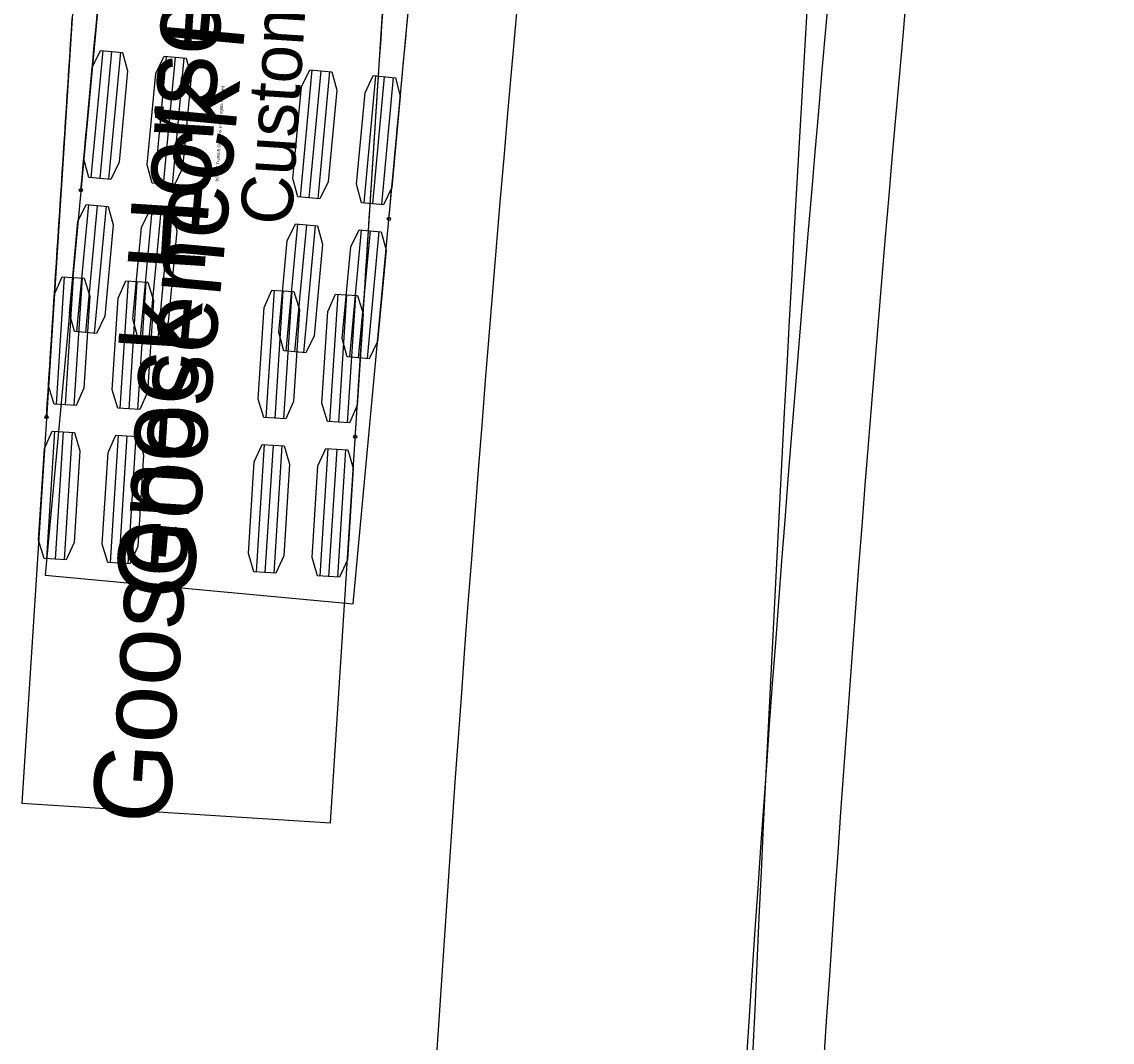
# Model space of a CAD drawing. Extents: x -14 to 1565148, y -25 to 642856.
# Drawn here: x 1564790.38 to 1564818.58, y 636076.25 to 636102.63 of the extents above; entities that cross this region are included whole.
import ezdxf

# ---------------------------------------------------------------- set-up
doc = ezdxf.new("R2010")
doc.units = 0
for name, color, linetype in [('DR_P_Drainage_Area', 7, 'Continuous'), ('DR_P_Underdrain', 7, 'Continuous'), ('GE_P_Alignment', 7, 'Continuous'), ('MT_P_Cells', 7, 'Continuous'), ('PF_P_Grade_Line', 7, 'Continuous'), ('PV_X_EOP', 7, 'Continuous')]:
    doc.layers.add(name, color=color, linetype=linetype)

msp = doc.modelspace()

# ---------------------------------------------------------------- linework, layer by layer
at = {"layer": 'DR_P_Drainage_Area'}
msp.add_arc((1566787.273, 635986.808), 1980, 175.493678, 179.898828, dxfattribs=at)
at = {"layer": 'DR_P_Underdrain'}
msp.add_arc((1565898.839, 636005.315), 1090, 172.336069, 179.46316, dxfattribs=at)
at = {"layer": 'GE_P_Alignment'}
msp.add_arc((1565898.839, 636005.315), 1092, 172.336069, 179.46316, dxfattribs=at)
at = {"layer": 'MT_P_Cells'}
for p, q in [((1564792.682, 636118.358), (1564790.385, 636082.431)), ((1564798.368, 636081.921), (1564800.666, 636117.847)), ((1564791.484, 636096.039), (1564791.274, 636092.745)), ((1564791.713, 636096.024), (1564791.503, 636092.731)), ((1564791.942, 636096.009), (1564791.731, 636092.716)), ((1564793.131, 636095.933), (1564792.92, 636092.64)), ((1564793.36, 636095.919), (1564793.149, 636092.626)), ((1564793.588, 636095.904), (1564793.378, 636092.611)), ((1564796.907, 636095.692), (1564796.696, 636092.399)), ((1564797.135, 636095.677), (1564796.925, 636092.384)), ((1564797.364, 636095.663), (1564797.153, 636092.369)), ((1564798.553, 636095.587), (1564798.343, 636092.293)), ((1564798.782, 636095.572), (1564798.571, 636092.279)), ((1564799.011, 636095.557), (1564798.8, 636092.264)), ((1564791.229, 636092.047), (1564791.019, 636088.754)), ((1564791.458, 636092.032), (1564791.247, 636088.739)), ((1564791.687, 636092.018), (1564791.476, 636088.724)), ((1564792.876, 636091.942), (1564792.665, 636088.648)), ((1564793.104, 636091.927), (1564792.894, 636088.634)), ((1564793.333, 636091.912), (1564793.123, 636088.619)), ((1564796.651, 636091.7), (1564796.441, 636088.407)), ((1564796.88, 636091.685), (1564796.669, 636088.392)), ((1564797.109, 636091.671), (1564796.898, 636088.378)), ((1564798.298, 636091.595), (1564798.087, 636088.302)), ((1564798.527, 636091.58), (1564798.316, 636088.287)), ((1564798.755, 636091.566), (1564798.545, 636088.272)), ((1564790.385, 636082.431), (1564798.368, 636081.921))]:
    msp.add_line(p, q, dxfattribs=at)
for points in [[(1564799.006, 636091.9), (1564799.028, 636092.233), (1564799.049, 636092.566), (1564799.07, 636092.898), (1564799.092, 636093.23), (1564799.113, 636093.563), (1564799.134, 636093.895), (1564799.155, 636094.227), (1564799.177, 636094.559), (1564799.198, 636094.891), (1564799.219, 636095.223), (1564799.241, 636095.555), (1564799.262, 636095.887), (1564799.283, 636096.22), (1564799.305, 636096.552), (1564799.326, 636096.884), (1564799.347, 636097.216), (1564799.369, 636097.548), (1564799.39, 636097.88), (1564799.412, 636098.211), (1564799.433, 636098.543), (1564799.455, 636098.875), (1564799.476, 636099.207), (1564799.498, 636099.539), (1564799.519, 636099.871), (1564799.541, 636100.203), (1564799.563, 636100.535), (1564799.585, 636100.866), (1564799.606, 636101.198), (1564799.628, 636101.53), (1564799.65, 636101.862), (1564799.672, 636102.193), (1564799.694, 636102.525), (1564799.716, 636102.857)], [(1564791.023, 636092.411), (1564791.044, 636092.743), (1564791.065, 636093.076), (1564791.087, 636093.409), (1564791.108, 636093.741), (1564791.129, 636094.073), (1564791.15, 636094.406), (1564791.172, 636094.738), (1564791.193, 636095.071), (1564791.214, 636095.403), (1564791.236, 636095.735), (1564791.257, 636096.068), (1564791.278, 636096.4), (1564791.3, 636096.733), (1564791.321, 636097.065), (1564791.342, 636097.398), (1564791.364, 636097.73), (1564791.385, 636098.063), (1564791.407, 636098.395), (1564791.428, 636098.728), (1564791.45, 636099.061), (1564791.472, 636099.393), (1564791.493, 636099.726), (1564791.515, 636100.058), (1564791.536, 636100.391), (1564791.558, 636100.724), (1564791.58, 636101.056), (1564791.602, 636101.389), (1564791.623, 636101.722), (1564791.645, 636102.054), (1564791.667, 636102.387), (1564791.689, 636102.72)]]:
    msp.add_lwpolyline(points, dxfattribs=at)
for points in [[(1564791.428, 636096.042), (1564791.999, 636096.006), (1564792.141, 636095.534), (1564791.989, 636093.163), (1564791.788, 636092.713), (1564791.217, 636092.749), (1564791.075, 636093.221), (1564791.226, 636095.592)], [(1564793.074, 636095.937), (1564793.645, 636095.901), (1564793.788, 636095.428), (1564793.636, 636093.057), (1564793.435, 636092.607), (1564792.864, 636092.644), (1564792.721, 636093.116), (1564792.873, 636095.487)], [(1564796.85, 636095.696), (1564797.421, 636095.659), (1564797.563, 636095.187), (1564797.412, 636092.816), (1564797.21, 636092.366), (1564796.639, 636092.402), (1564796.497, 636092.874), (1564796.648, 636095.246)], [(1564798.497, 636095.59), (1564799.067, 636095.554), (1564799.21, 636095.082), (1564799.058, 636092.711), (1564798.857, 636092.26), (1564798.286, 636092.297), (1564798.143, 636092.769), (1564798.295, 636095.14)], [(1564791.172, 636092.05), (1564791.743, 636092.014), (1564791.886, 636091.542), (1564791.734, 636089.171), (1564791.533, 636088.721), (1564790.962, 636088.757), (1564790.819, 636089.229), (1564790.971, 636091.6)], [(1564792.819, 636091.945), (1564793.39, 636091.909), (1564793.532, 636091.437), (1564793.381, 636089.065), (1564793.179, 636088.615), (1564792.608, 636088.652), (1564792.466, 636089.124), (1564792.618, 636091.495)], [(1564796.595, 636091.704), (1564797.166, 636091.667), (1564797.308, 636091.195), (1564797.156, 636088.824), (1564796.955, 636088.374), (1564796.384, 636088.41), (1564796.242, 636088.883), (1564796.393, 636091.254)], [(1564798.241, 636091.598), (1564798.812, 636091.562), (1564798.955, 636091.09), (1564798.803, 636088.719), (1564798.602, 636088.269), (1564798.031, 636088.305), (1564797.888, 636088.777), (1564798.04, 636091.148)]]:
    msp.add_lwpolyline(points, close=True, dxfattribs=at)
for centre in [(1564791.023, 636092.411), (1564799.006, 636091.9)]:
    msp.add_circle(centre, 0.0417, dxfattribs=at)
at = {"layer": 'PF_P_Grade_Line'}
for p, q in [((1564794.313, 636124.165), (1564790.986, 636088.319)), ((1564798.952, 636087.579), (1564802.279, 636123.425)), ((1564792.476, 636101.889), (1564792.171, 636098.603)), ((1564792.704, 636101.868), (1564792.399, 636098.582)), ((1564792.932, 636101.847), (1564792.627, 636098.561)), ((1564794.119, 636101.737), (1564793.814, 636098.451)), ((1564794.347, 636101.715), (1564794.042, 636098.429)), ((1564794.575, 636101.694), (1564794.27, 636098.408)), ((1564797.886, 636101.387), (1564797.581, 636098.101)), ((1564798.114, 636101.366), (1564797.809, 636098.08)), ((1564798.342, 636101.344), (1564798.037, 636098.059)), ((1564799.529, 636101.234), (1564799.224, 636097.948)), ((1564799.757, 636101.213), (1564799.452, 636097.927)), ((1564799.985, 636101.192), (1564799.68, 636097.906)), ((1564792.106, 636097.906), (1564791.801, 636094.62)), ((1564792.334, 636097.885), (1564792.029, 636094.599)), ((1564792.563, 636097.864), (1564792.258, 636094.578)), ((1564793.749, 636097.754), (1564793.444, 636094.468)), ((1564793.977, 636097.732), (1564793.672, 636094.447)), ((1564794.206, 636097.711), (1564793.901, 636094.425)), ((1564797.516, 636097.404), (1564797.211, 636094.118)), ((1564797.744, 636097.383), (1564797.439, 636094.097)), ((1564797.973, 636097.362), (1564797.668, 636094.076)), ((1564799.159, 636097.251), (1564798.854, 636093.966)), ((1564799.387, 636097.23), (1564799.082, 636093.944)), ((1564799.616, 636097.209), (1564799.311, 636093.923)), ((1564790.986, 636088.319), (1564798.952, 636087.579))]:
    msp.add_line(p, q, dxfattribs=at)
for points in [[(1564791.91, 636098.276), (1564791.941, 636098.608), (1564791.972, 636098.941), (1564792.003, 636099.273), (1564792.034, 636099.606), (1564792.065, 636099.938), (1564792.096, 636100.271), (1564792.127, 636100.603), (1564792.157, 636100.936), (1564792.188, 636101.268), (1564792.219, 636101.601), (1564792.25, 636101.933), (1564792.281, 636102.266), (1564792.312, 636102.598), (1564792.343, 636102.931)], [(1564799.876, 636097.536), (1564799.907, 636097.869), (1564799.938, 636098.201), (1564799.969, 636098.534), (1564800, 636098.866), (1564800.03, 636099.198), (1564800.061, 636099.53), (1564800.092, 636099.863), (1564800.123, 636100.195), (1564800.154, 636100.527), (1564800.185, 636100.86), (1564800.216, 636101.192), (1564800.247, 636101.524), (1564800.278, 636101.856), (1564800.309, 636102.188), (1564800.34, 636102.521), (1564800.371, 636102.853)]]:
    msp.add_lwpolyline(points, dxfattribs=at)
for points in [[(1564792.419, 636101.894), (1564792.989, 636101.841), (1564793.118, 636101.365), (1564792.898, 636099), (1564792.684, 636098.556), (1564792.114, 636098.608), (1564791.985, 636099.084), (1564792.205, 636101.45)], [(1564794.062, 636101.742), (1564794.632, 636101.689), (1564794.761, 636101.213), (1564794.541, 636098.847), (1564794.327, 636098.403), (1564793.757, 636098.456), (1564793.628, 636098.932), (1564793.848, 636101.298)], [(1564797.829, 636101.392), (1564798.399, 636101.339), (1564798.528, 636100.863), (1564798.308, 636098.497), (1564798.094, 636098.053), (1564797.524, 636098.106), (1564797.396, 636098.582), (1564797.615, 636100.948)], [(1564799.472, 636101.24), (1564800.042, 636101.187), (1564800.171, 636100.711), (1564799.951, 636098.345), (1564799.737, 636097.901), (1564799.167, 636097.954), (1564799.038, 636098.43), (1564799.258, 636100.795)], [(1564792.05, 636097.911), (1564792.619, 636097.859), (1564792.748, 636097.383), (1564792.528, 636095.017), (1564792.314, 636094.573), (1564791.745, 636094.626), (1564791.616, 636095.101), (1564791.835, 636097.467)], [(1564793.693, 636097.759), (1564794.262, 636097.706), (1564794.391, 636097.23), (1564794.171, 636094.864), (1564793.957, 636094.42), (1564793.388, 636094.473), (1564793.259, 636094.949), (1564793.478, 636097.315)], [(1564797.46, 636097.409), (1564798.029, 636097.356), (1564798.158, 636096.88), (1564797.939, 636094.515), (1564797.724, 636094.07), (1564797.155, 636094.123), (1564797.026, 636094.599), (1564797.245, 636096.965)], [(1564799.103, 636097.257), (1564799.672, 636097.204), (1564799.801, 636096.728), (1564799.581, 636094.362), (1564799.367, 636093.918), (1564798.798, 636093.971), (1564798.669, 636094.447), (1564798.888, 636096.813)]]:
    msp.add_lwpolyline(points, close=True, dxfattribs=at)
for centre in [(1564791.91, 636098.276), (1564799.876, 636097.536)]:
    msp.add_circle(centre, 0.0417, dxfattribs=at)
at = {"layer": 'PV_X_EOP'}
msp.add_arc((1565898.839, 636005.315), 1100, 172.336069, 180.049147, dxfattribs=at)

# ---------------------------------------------------------------- texts
at = {"layer": 'MT_P_Cells'}
for s, height, p in [('Gooseneck Horse Trailer', 2, (1564794.195, 636081.853)), ('Custom', 1.3333, (1564797.358, 636097.35)), ('(c) 2022 Transoft Solutions, Inc. All rights reserved.', 0.08, (1564795.461, 636098.502))]:
    msp.add_text(s, height=height, rotation=86.3409, dxfattribs=at).set_placement(p)
at = {"layer": 'PF_P_Grade_Line'}
msp.add_text('Gooseneck Horse Trailer', height=2, rotation=84.6968, dxfattribs=at).set_placement((1564794.779, 636087.632))

doc.saveas('drawing.dxf')
